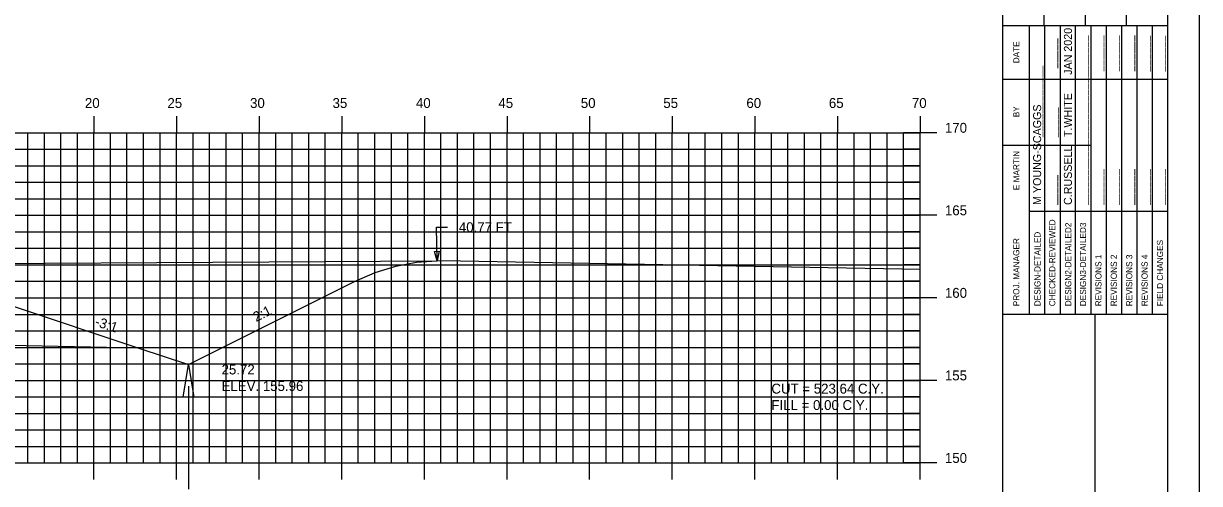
# Model space of a CAD drawing. Extents: x 1143198 to 1143368, y 608981 to 609091.
# Drawn here: x 1143297.1 to 1143368.2, y 609019.1 to 609047 of the extents above; entities that cross this region are included whole.
import ezdxf

# ---------------------------------------------------------------- set-up
doc = ezdxf.new("R2010")
doc.units = 0
for name, color, linetype in [('ANNOTATION', 7, 'Continuous'), ('BORDER', 7, 'Continuous'), ('D_Drainage_Ditch_Line', 7, 'Continuous'), ('D_Roadway_SlopeLines', 7, 'Continuous'), ('D_Roadway_SubGrade', 7, 'Continuous'), ('D_Text_Standard', 7, 'Continuous'), ('H_V ANNOTATION', 7, 'Continuous'), ('MAJOR', 7, 'Continuous'), ('MINOR', 7, 'Continuous'), ('PLOT BOUNDARY', 7, 'Continuous'), ('S_Roadway_Centerline', 7, 'Continuous')]:
    doc.layers.add(name, color=color, linetype=linetype)

msp = doc.modelspace()

# ---------------------------------------------------------------- linework, layer by layer
msp.add_lwpolyline([(1143240.971, 609032.398), (1143242.221, 609032.303), (1143243.471, 609032.057), (1143244.721, 609031.659), (1143245.971, 609031.11), (1143255.598, 609026.296), (1143258.598, 609027.296), (1143266.322, 609029.871), (1143266.323, 609029.871), (1143270.323, 609030.031), (1143281.323, 609030.251), (1143292.323, 609030.031), (1143296.323, 609029.871), (1143304.047, 609027.296), (1143307.047, 609026.296), (1143317.091, 609031.319), (1143318.341, 609031.867), (1143319.591, 609032.26), (1143320.841, 609032.5), (1143322.091, 609032.585)])
at = {"layer": 'BORDER'}
for p, q in [((1143356.323, 608984.335), (1143356.323, 609089.335)), ((1143358.823, 609046.838), (1143358.823, 609055.485)), ((1143361.323, 609046.838), (1143361.323, 609055.485)), ((1143363.823, 609046.838), (1143363.823, 609055.485)), ((1143356.323, 609046.838), (1143366.323, 609046.838)), ((1143356.323, 609029.338), (1143366.323, 609029.338)), ((1143361.914, 608994.338), (1143361.914, 609029.338))]:
    msp.add_line(p, q, dxfattribs=at)
msp.add_lwpolyline([(1143206.323, 608984.335), (1143366.323, 608984.335), (1143366.323, 609089.335), (1143206.323, 609089.335)], close=True, dxfattribs=at)
for points in [[(1143357.938, 609043.588), (1143357.938, 609046.838)], [(1143358.871, 609029.341), (1143358.871, 609046.838)], [(1143359.802, 609046.838), (1143359.802, 609029.341)], [(1143360.734, 609029.341), (1143360.734, 609046.838)], [(1143361.666, 609029.341), (1143361.666, 609046.838)], [(1143362.597, 609029.341), (1143362.597, 609046.838)], [(1143363.529, 609029.341), (1143363.529, 609046.838)], [(1143364.461, 609029.341), (1143364.461, 609046.838)], [(1143365.393, 609029.341), (1143365.393, 609046.838)], [(1143357.939, 609029.341), (1143357.939, 609046.132)], [(1143356.323, 609043.588), (1143366.323, 609043.588)], [(1143356.323, 609039.588), (1143357.939, 609039.588)], [(1143357.938, 609039.588), (1143361.665, 609039.588)], [(1143357.938, 609035.588), (1143366.323, 609035.588)]]:
    msp.add_lwpolyline(points, dxfattribs=at)
at = {"layer": 'D_Drainage_Ditch_Line'}
msp.add_line((1143307.047, 609024.984), (1143307.046, 609018.741), dxfattribs=at)
msp.add_lwpolyline([(1143307.375, 609024.328), (1143306.718, 609024.328), (1143307.047, 609026.296)], close=True, dxfattribs=at)
at = {"layer": 'D_Roadway_SlopeLines'}
for points in [[(1143307.047, 609026.296), (1143317.091, 609031.319), (1143318.341, 609031.867), (1143319.591, 609032.26), (1143320.841, 609032.5), (1143322.091, 609032.585)], [(1143304.047, 609027.296), (1143307.047, 609026.296)]]:
    msp.add_lwpolyline(points, dxfattribs=at)
at = {"layer": 'D_Roadway_SubGrade'}
msp.add_lwpolyline([(1143292.323, 609029.614), (1143292.323, 609029.781), (1143296.323, 609029.621), (1143296.323, 609029.871), (1143296.323, 609029.871), (1143304.047, 609027.296), (1143292.323, 609027.531)], close=True, dxfattribs=at)
at = {"layer": 'D_Text_Standard'}
msp.add_lwpolyline([(1143322.091, 609032.569), (1143322.049, 609034.615), (1143322.729, 609034.615)], dxfattribs=at)
msp.add_lwpolyline([(1143322.091, 609032.569), (1143321.934, 609033.148), (1143322.225, 609033.154)], close=True, dxfattribs=at)
at = {"layer": 'MAJOR'}
for p, q in [((1143301.323, 609041.337), (1143301.323, 609040.335)), ((1143306.323, 609041.337), (1143306.323, 609040.335)), ((1143311.323, 609041.337), (1143311.323, 609040.335)), ((1143316.323, 609041.337), (1143316.323, 609040.335)), ((1143321.323, 609041.337), (1143321.323, 609040.335)), ((1143326.323, 609041.337), (1143326.323, 609040.335)), ((1143331.323, 609041.337), (1143331.323, 609040.335)), ((1143336.323, 609041.337), (1143336.323, 609040.335)), ((1143341.323, 609041.337), (1143341.323, 609040.335)), ((1143346.323, 609041.337), (1143346.323, 609040.335)), ((1143351.323, 609041.337), (1143351.323, 609040.335)), ((1143211.323, 609040.335), (1143351.323, 609040.335)), ((1143211.323, 609040.335), (1143351.323, 609040.335)), ((1143301.323, 609020.335), (1143301.323, 609040.335)), ((1143306.323, 609020.335), (1143306.323, 609040.335)), ((1143311.323, 609020.335), (1143311.323, 609040.335)), ((1143316.323, 609020.335), (1143316.323, 609040.335)), ((1143321.323, 609020.335), (1143321.323, 609040.335)), ((1143326.323, 609020.335), (1143326.323, 609040.335)), ((1143331.323, 609020.335), (1143331.323, 609040.335)), ((1143336.323, 609020.335), (1143336.323, 609040.335)), ((1143341.323, 609020.335), (1143341.323, 609040.335)), ((1143346.323, 609020.335), (1143346.323, 609040.335)), ((1143352.325, 609040.335), (1143350.321, 609040.335)), ((1143351.323, 609020.335), (1143351.323, 609040.335)), ((1143351.323, 609020.335), (1143351.323, 609040.335)), ((1143211.323, 609035.335), (1143351.323, 609035.335)), ((1143352.325, 609035.335), (1143350.321, 609035.335)), ((1143211.323, 609030.335), (1143351.323, 609030.335)), ((1143352.325, 609030.335), (1143350.321, 609030.335)), ((1143211.323, 609025.335), (1143351.323, 609025.335)), ((1143352.325, 609025.335), (1143350.321, 609025.335)), ((1143211.323, 609020.335), (1143351.323, 609020.335)), ((1143211.323, 609020.335), (1143351.323, 609020.335)), ((1143301.323, 609019.333), (1143301.323, 609020.335)), ((1143306.323, 609019.333), (1143306.323, 609020.335)), ((1143311.323, 609019.333), (1143311.323, 609020.335)), ((1143316.323, 609019.333), (1143316.323, 609020.335)), ((1143321.323, 609019.333), (1143321.323, 609020.335)), ((1143326.323, 609019.333), (1143326.323, 609020.335)), ((1143331.323, 609019.333), (1143331.323, 609020.335)), ((1143336.323, 609019.333), (1143336.323, 609020.335)), ((1143341.323, 609019.333), (1143341.323, 609020.335)), ((1143346.323, 609019.333), (1143346.323, 609020.335)), ((1143352.325, 609020.335), (1143350.321, 609020.335)), ((1143351.323, 609019.333), (1143351.323, 609020.335))]:
    msp.add_line(p, q, dxfattribs=at)
at = {"layer": 'MINOR'}
for p, q in [((1143297.323, 609020.335), (1143297.323, 609040.335)), ((1143298.323, 609020.335), (1143298.323, 609040.335)), ((1143299.323, 609020.335), (1143299.323, 609040.335)), ((1143300.323, 609020.335), (1143300.323, 609040.335)), ((1143302.323, 609020.335), (1143302.323, 609040.335)), ((1143303.323, 609020.335), (1143303.323, 609040.335)), ((1143304.323, 609020.335), (1143304.323, 609040.335)), ((1143305.323, 609020.335), (1143305.323, 609040.335)), ((1143307.323, 609020.335), (1143307.323, 609040.335)), ((1143308.323, 609020.335), (1143308.323, 609040.335)), ((1143309.323, 609020.335), (1143309.323, 609040.335)), ((1143310.323, 609020.335), (1143310.323, 609040.335)), ((1143312.323, 609020.335), (1143312.323, 609040.335)), ((1143313.323, 609020.335), (1143313.323, 609040.335)), ((1143314.323, 609020.335), (1143314.323, 609040.335)), ((1143315.323, 609020.335), (1143315.323, 609040.335)), ((1143317.323, 609020.335), (1143317.323, 609040.335)), ((1143318.323, 609020.335), (1143318.323, 609040.335)), ((1143319.323, 609020.335), (1143319.323, 609040.335)), ((1143320.323, 609020.335), (1143320.323, 609040.335)), ((1143322.323, 609020.335), (1143322.323, 609040.335)), ((1143323.323, 609020.335), (1143323.323, 609040.335)), ((1143324.323, 609020.335), (1143324.323, 609040.335)), ((1143325.323, 609020.335), (1143325.323, 609040.335)), ((1143327.323, 609020.335), (1143327.323, 609040.335)), ((1143328.323, 609020.335), (1143328.323, 609040.335)), ((1143329.323, 609020.335), (1143329.323, 609040.335)), ((1143330.323, 609020.335), (1143330.323, 609040.335)), ((1143332.323, 609020.335), (1143332.323, 609040.335)), ((1143333.323, 609020.335), (1143333.323, 609040.335)), ((1143334.323, 609020.335), (1143334.323, 609040.335)), ((1143335.323, 609020.335), (1143335.323, 609040.335)), ((1143337.323, 609020.335), (1143337.323, 609040.335)), ((1143338.323, 609020.335), (1143338.323, 609040.335)), ((1143339.323, 609020.335), (1143339.323, 609040.335)), ((1143340.323, 609020.335), (1143340.323, 609040.335)), ((1143342.323, 609020.335), (1143342.323, 609040.335)), ((1143343.323, 609020.335), (1143343.323, 609040.335)), ((1143344.323, 609020.335), (1143344.323, 609040.335)), ((1143345.323, 609020.335), (1143345.323, 609040.335)), ((1143347.323, 609020.335), (1143347.323, 609040.335)), ((1143348.323, 609020.335), (1143348.323, 609040.335)), ((1143349.323, 609020.335), (1143349.323, 609040.335)), ((1143350.323, 609020.335), (1143350.323, 609040.335)), ((1143211.323, 609039.335), (1143351.323, 609039.335)), ((1143351.323, 609039.335), (1143350.321, 609039.335)), ((1143211.323, 609038.335), (1143351.323, 609038.335)), ((1143351.323, 609038.335), (1143350.321, 609038.335)), ((1143211.323, 609037.335), (1143351.323, 609037.335)), ((1143351.323, 609037.335), (1143350.321, 609037.335)), ((1143211.323, 609036.335), (1143351.323, 609036.335)), ((1143351.323, 609036.335), (1143350.321, 609036.335)), ((1143211.323, 609034.335), (1143351.323, 609034.335)), ((1143351.323, 609034.335), (1143350.321, 609034.335)), ((1143211.323, 609033.335), (1143351.323, 609033.335)), ((1143351.323, 609033.335), (1143350.321, 609033.335)), ((1143211.323, 609032.335), (1143351.323, 609032.335)), ((1143351.323, 609032.335), (1143350.321, 609032.335)), ((1143211.323, 609031.335), (1143351.323, 609031.335)), ((1143351.323, 609031.335), (1143350.321, 609031.335)), ((1143211.323, 609029.335), (1143351.323, 609029.335)), ((1143351.323, 609029.335), (1143350.321, 609029.335)), ((1143211.323, 609028.335), (1143351.323, 609028.335)), ((1143351.323, 609028.335), (1143350.321, 609028.335)), ((1143211.323, 609027.335), (1143351.323, 609027.335)), ((1143351.323, 609027.335), (1143350.321, 609027.335)), ((1143211.323, 609026.335), (1143351.323, 609026.335)), ((1143351.323, 609026.335), (1143350.321, 609026.335)), ((1143211.323, 609024.335), (1143351.323, 609024.335)), ((1143351.323, 609024.335), (1143350.321, 609024.335)), ((1143211.323, 609023.335), (1143351.323, 609023.335)), ((1143351.323, 609023.335), (1143350.321, 609023.335)), ((1143211.323, 609022.335), (1143351.323, 609022.335)), ((1143351.323, 609022.335), (1143350.321, 609022.335)), ((1143211.323, 609021.335), (1143351.323, 609021.335)), ((1143351.323, 609021.335), (1143350.321, 609021.335))]:
    msp.add_line(p, q, dxfattribs=at)
at = {"layer": 'PLOT BOUNDARY'}
msp.add_lwpolyline([(1143198.23, 608981.276), (1143368.23, 608981.276), (1143368.23, 609091.276), (1143198.23, 609091.276)], close=True, dxfattribs=at)
at = {"layer": 'S_Roadway_Centerline'}
msp.add_lwpolyline([(1143294.969, 609032.411), (1143322.054, 609032.585), (1143323.118, 609032.59), (1143323.498, 609032.584), (1143351.323, 609032.081)], dxfattribs=at)

# ---------------------------------------------------------------- texts
at = {"layer": 'ANNOTATION'}
for s, rotation, p in [('2:1', 26.56505, (1143311.141, 609028.862)), ('-3:1', 341.56521, (1143301.334, 609028.655))]:
    msp.add_text(s, height=0.6, rotation=rotation, dxfattribs=at).set_placement(p)
at = {"layer": 'BORDER'}
for s, height, p in [('JAN 2020', 0.4845, (1143360.51, 609043.843)), ('DATE', 0.3714, (1143357.328, 609044.544)), ('_____', 0.4845, (1143359.541, 609044.243)), ('______', 0.4845, (1143361.404, 609044.063)), ('______', 0.4845, (1143362.336, 609044.065)), ('______', 0.4845, (1143363.267, 609044.067)), ('______', 0.4845, (1143364.199, 609044.067)), ('______', 0.4845, (1143365.131, 609044.036)), ('______', 0.4845, (1143366.062, 609044.036)), ('____________', 0.48455, (1143358.646, 609040.073)), ('____________', 0.48455, (1143361.404, 609040.073)), ('T.WHITE', 0.4845, (1143360.51, 609040.073)), ('M YOUNG-SCAGGS', 0.48455, (1143358.646, 609035.961)), ('BY', 0.3714, (1143357.328, 609041.273)), ('_____', 0.4845, (1143359.578, 609040.073)), ('____________', 0.48455, (1143361.404, 609035.961)), ('E MARTIN', 0.3727, (1143357.328, 609036.855)), ('C.RUSSELL', 0.4845, (1143360.51, 609035.961)), ('_____', 0.4845, (1143359.541, 609035.961)), ('______', 0.4845, (1143362.336, 609035.961)), ('______', 0.4845, (1143363.267, 609035.961)), ('______', 0.4845, (1143364.199, 609035.961)), ('______', 0.4845, (1143365.131, 609035.961)), ('______', 0.4845, (1143366.062, 609035.961)), ('CHECKED-REVIEWED', 0.37275, (1143359.504, 609029.826)), ('DESIGN3-DETAILED3', 0.37275, (1143361.368, 609029.826)), ('DESIGN-DETAILED', 0.37275, (1143358.61, 609029.826)), ('DESIGN2-DETAILED2', 0.37275, (1143360.473, 609029.826)), ('PROJ. MANAGER', 0.37275, (1143357.328, 609029.826)), ('FIELD CHANGES', 0.37275, (1143366.026, 609029.826)), ('REVISIONS 1', 0.37275, (1143362.299, 609029.826)), ('REVISIONS 2', 0.37275, (1143363.231, 609029.826)), ('REVISIONS 3', 0.37275, (1143364.163, 609029.826)), ('REVISIONS 4', 0.37275, (1143365.094, 609029.826))]:
    msp.add_text(s, height=height, rotation=90, dxfattribs=at).set_placement(p)
at = {"layer": 'D_Text_Standard'}
for s, p in [('40.77 FT', (1143323.409, 609034.315)), ('25.72', (1143309.047, 609025.696)), ('ELEV. 155.96', (1143309.047, 609024.694)), ('CUT = 523.64 C.Y.', (1143342.323, 609024.535)), ('FILL = 0.00 C.Y.', (1143342.323, 609023.539))]:
    msp.add_text(s, height=0.6, dxfattribs=at).set_placement(p)
at = {"layer": 'H_V ANNOTATION'}
for s, p in [('20', (1143300.777, 609041.835)), ('25', (1143305.769, 609041.835)), ('30', (1143310.772, 609041.835)), ('35', (1143315.764, 609041.835)), ('40', (1143320.809, 609041.835)), ('45', (1143325.801, 609041.835)), ('50', (1143330.788, 609041.835)), ('55', (1143335.78, 609041.835)), ('60', (1143340.809, 609041.835)), ('65', (1143345.801, 609041.835)), ('70', (1143350.825, 609041.835)), ('170', (1143352.823, 609040.335)), ('165', (1143352.823, 609035.335)), ('160', (1143352.823, 609030.335)), ('155', (1143352.823, 609025.335)), ('150', (1143352.823, 609020.335))]:
    msp.add_text(s, height=0.6, dxfattribs=at).set_placement(p)

doc.saveas('drawing.dxf')
